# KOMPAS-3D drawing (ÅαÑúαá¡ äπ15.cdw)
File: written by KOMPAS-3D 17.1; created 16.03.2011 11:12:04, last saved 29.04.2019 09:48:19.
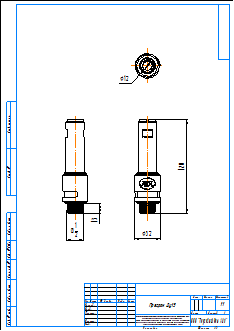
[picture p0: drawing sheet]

Title block, sheet 1: name: Прегран Ду15; material: Внимание! Данный продукт является объектом авторского права ООО «Торговый Дом АДЛ». / Запрещается изменение, копирование, распространение / (в том числе путем копирования на другие сайты и ресурсы в Интернете) / или любое иное использование информации и объектов без предварительного / согласия правообладателя (ООО «Торговый Дом АДЛ»).; scale: 1:1; sheets: 1; organisation: ООО "Торговый дом АДЛ"; sheet format: A3; stored path: C:\Users\tra\Desktop\2д чертежи\Предохранительные клапаны ПРЕГРАН\ПРЕГРАН 495\ПРЕГРАН КПП 495-05-25-ОМЗ\KOMPAS 2D\Прегран Ду15.cdw

Views: Спереди 1, Проекционный вид 2, Проекционный вид 3
Dimensions and other numbers on the sheet: 120; 32; 13; 12; 1:1; 1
